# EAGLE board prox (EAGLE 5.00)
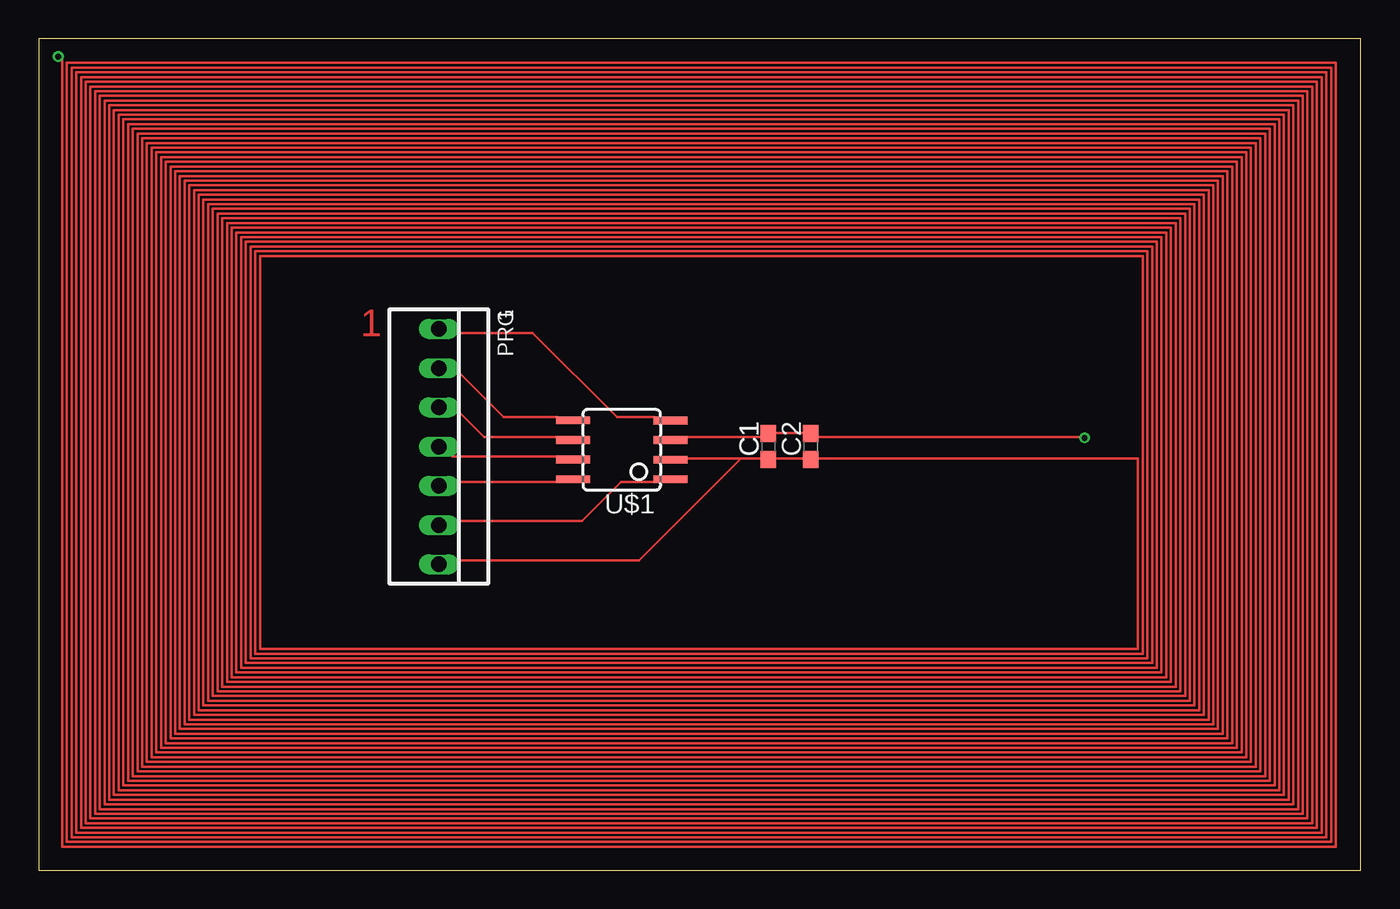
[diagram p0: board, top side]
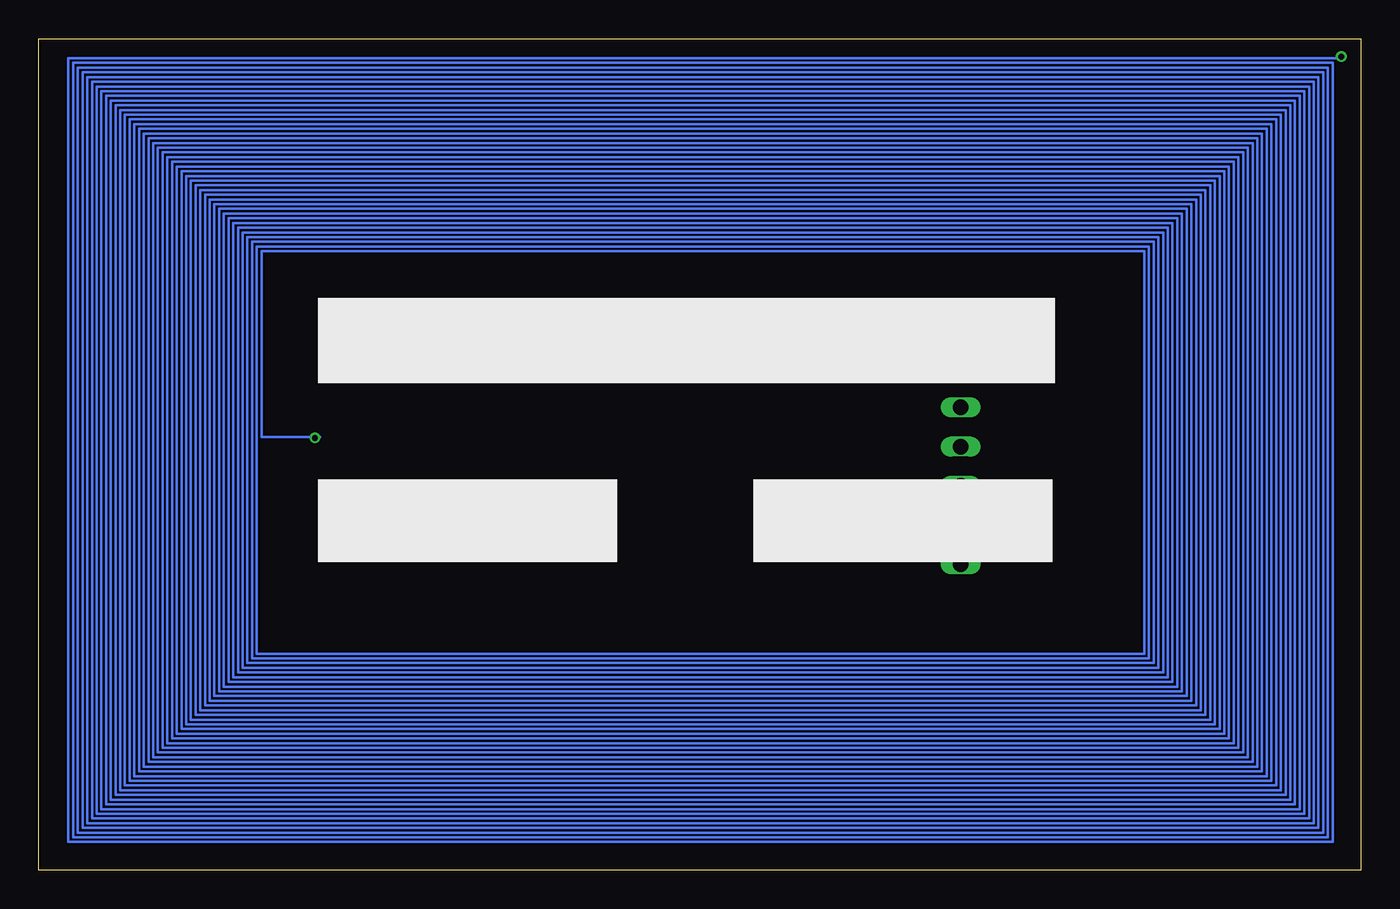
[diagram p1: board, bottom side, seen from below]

Size 85.6 x 53.85 mm. Coordinates in mm from the lower left corner, seen from the top.
Outline: 0,0 85.6,0 85.6,53.85 0,53.85 0,0
Copper layers (1*16): Top 0.035mm / dielectric 1.5mm / Bottom 0.035mm
Design rules "default *": minimum track width 6mil, minimum drill 15mil, track to track 6mil, track to pad 6mil, pad to pad 6mil, via to via 6mil, smd to smd 6mil, copper to edge 40mil, drill to drill 15mil, minimum pad ring 6mil, minimum via ring 6mil, stop-mask expansion 4mil, vias tented up to drill 0mil, thermal gap 10mil

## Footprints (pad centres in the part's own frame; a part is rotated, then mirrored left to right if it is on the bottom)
C0603 = smd 1.1 x 1: 1 -0.85,0; 2 0.85,0
22-23-2071 = drill 1 long: 1 -7.62,0; 2 -5.08,0; 3 -2.54,0; 4 0,0; 5 2.54,0; 6 5.08,0; 7 7.62,0
SOIC8 = smd 0.5 x 2.2: 1 -1.905,-3.154; 2 -0.645,-3.154; 3 0.625,-3.154; 4 1.895,-3.154; 5 1.905,3.154; 6 0.635,3.154; 7 -0.635,3.154; 8 -1.905,3.154

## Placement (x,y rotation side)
C1  [C0603]  47.24,27.43 90 top
C2  [C0603]  49.99,27.43 90 top
PRG  [22-23-2071]  25.91,27.43 270 top
U$1  TINY25/45/85-20SU  [SOIC8]  37.74,27.23 90 top

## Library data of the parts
C1 C2 = rcl
PRG = con-molex
U$1 = avr-7

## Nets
N$1: PRG.1 U$1.4
N$2: PRG.2 U$1.5
N$3: PRG.3 U$1.6
N$4: PRG.4 U$1.7
N$5: PRG.5 U$1.8
N$6: PRG.6 U$1.1
N$7: C1.1 C2.1 PRG.7 U$1.2
N$8: C1.2 C2.2 U$1.3

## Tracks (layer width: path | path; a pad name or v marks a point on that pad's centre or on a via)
N$1
  Top 0.152: U$1.4 39.88,29.34 37.44,29.34 31.98,34.8 27.18,34.8 PRG.1
N$2
  Top 0.152: U$1.5 33.53,29.34 30.1,29.34 27.18,32.26 PRG.2
N$3
  Top 0.152: U$1.6 33.53,28.07 28.83,28.07 27.18,29.72 PRG.3
N$4
  Top 0.152: U$1.7 33.53,26.8 26.8,26.8 PRG.4
N$5
  Top 0.152: U$1.8 33.53,25.15 27.18,25.15 PRG.5
N$6
  Top 0.152: U$1.1 39.88,25.15 37.72,25.15 35.18,22.61 27.18,22.61 PRG.6
N$7
  Top 0.152: C2.1 49.53,26.67 47.62,26.67 C1.1 46.86,26.67 45.47,26.67 | 45.47,26.67 41.91,26.67 U$1.2 | 45.47,26.67 38.86,20.07 27.18,20.07 PRG.7
N$8
  Top 0.152: C2.2 49.53,28.32 47.62,28.32 C1.2 46.86,28.07 41.91,28.07 U$1.3
N$9
  Top 0.152: 50.14,26.67 71.17,26.67 71.17,14.33 14.33,14.33 14.33,39.78 71.48,39.78 71.48,14.02 14.02,14.02 14.02,40.08 71.78,40.08 71.78,13.72 13.72,13.72 13.72,40.39 72.08,40.39 72.08,13.41 13.41,13.41 13.41,40.69 72.39,40.69 72.39,13.11 13.11,13.11 13.11,41 72.69,41 72.69,12.8 12.8,12.8 12.8,41.3 73,41.3 73,12.5 12.5,12.5 12.5,41.6 73.3,41.6 73.3,12.19 12.19,12.19 12.19,41.91 73.61,41.91 73.61,11.89 11.89,11.89 11.89,42.22 73.91,42.22 73.91,11.58 11.58,11.58 11.58,42.52 74.22,42.52 74.22,11.28 11.28,11.28 11.28,42.82 74.52,42.82 74.52,10.97 10.97,10.97 10.97,43.13 74.83,43.13 74.83,10.67 10.67,10.67 10.67,43.43 75.13,43.43 75.13,10.36 10.36,10.36 10.36,43.74 75.44,43.74 75.44,10.06 10.06,10.06 10.06,44.04 75.74,44.04 75.74,9.75 9.75,9.75 9.75,44.35 76.05,44.35 76.05,9.45 9.45,9.45 9.45,44.65 76.35,44.65 76.35,9.14 9.14,9.14 9.14,44.96 76.66,44.96 76.66,8.84 8.84,8.84 8.84,45.26 76.96,45.26 76.96,8.53 8.53,8.53 8.53,45.57 77.27,45.57 77.27,8.23 8.23,8.23 8.23,45.87 77.57,45.87 77.57,7.92 7.92,7.92 7.92,46.18 77.88,46.18 77.88,7.62 7.62,7.62 7.62,46.48 78.18,46.48 78.18,7.32 7.32,7.32 7.32,46.79 78.49,46.79 78.49,7.01 7.01,7.01 7.01,47.09 78.79,47.09 78.79,6.71 6.71,6.71 6.71,47.4 79.1,47.4 79.1,6.4 6.4,6.4 6.4,47.7 79.4,47.7 79.4,6.1 6.1,6.1 6.1,48.01 79.7,48.01 79.7,5.79 5.79,5.79 5.79,48.31 80.01,48.31 80.01,5.49 5.49,5.49 5.49,48.62 80.31,48.62 80.31,5.18 5.18,5.18 5.18,48.92 80.62,48.92 80.62,4.88 4.88,4.88 4.88,49.23 80.92,49.23 80.92,4.57 4.57,4.57 4.57,49.53 81.23,49.53 81.23,4.27 4.27,4.27 4.27,49.84 81.53,49.84 81.53,3.96 3.96,3.96 3.96,50.14 81.84,50.14 81.84,3.66 3.66,3.66 3.66,50.44 82.14,50.44 82.14,3.35 3.35,3.35 3.35,50.75 82.45,50.75 82.45,3.05 3.05,3.05 3.05,51.05 82.75,51.05 82.75,2.74 2.74,2.74 2.74,51.36 83.06,51.36 83.06,2.44 2.44,2.44 2.44,51.66 83.36,51.66 83.36,2.13 2.13,2.13 2.13,51.97 83.67,51.97 83.67,1.83 1.83,1.83 1.83,52.27 83.97,52.27
N$10
  Top 0.152: 83.97,52.27 83.97,1.52 1.52,1.52 1.52,52.73
N$11
  Bottom 0.152: 67.36,28.04 71.17,28.04 71.17,40.08 14.02,40.08 14.02,14.02 71.48,14.02 71.48,40.39 13.72,40.39 13.72,13.72 71.78,13.72 71.78,40.69 13.41,40.69 13.41,13.41 72.08,13.41 72.08,41 13.11,41 13.11,13.11 72.39,13.11 72.39,41.3 12.8,41.3 12.8,12.8 72.69,12.8 72.69,41.6 12.5,41.6 12.5,12.5 73,12.5 73,41.91 12.19,41.91 12.19,12.19 73.3,12.19 73.3,42.22 11.89,42.22 11.89,11.89 73.61,11.89 73.61,42.52 11.58,42.52 11.58,11.58 73.91,11.58 73.91,42.82 11.28,42.82 11.28,11.28 74.22,11.28 74.22,43.13 10.97,43.13 10.97,10.97 74.52,10.97 74.52,43.43 10.67,43.43 10.67,10.67 74.83,10.67 74.83,43.74 10.36,43.74 10.36,10.36 75.13,10.36 75.13,44.04 10.06,44.04 10.06,10.06 75.44,10.06 75.44,44.35 9.75,44.35 9.75,9.75 75.74,9.75 75.74,44.65 9.45,44.65 9.45,9.45 76.05,9.45 76.05,44.96 9.14,44.96 9.14,9.14 76.35,9.14 76.35,45.26 8.84,45.26 8.84,8.84 76.66,8.84 76.66,45.57 8.53,45.57 8.53,8.53 76.96,8.53 76.96,45.87 8.23,45.87 8.23,8.23 77.27,8.23 77.27,46.18 7.92,46.18 7.92,7.92 77.57,7.92 77.57,46.48 7.62,46.48 7.62,7.62 77.88,7.62 77.88,46.79 7.32,46.79 7.32,7.32 78.18,7.32 78.18,47.09 7.01,47.09 7.01,7.01 78.49,7.01 78.49,47.4 6.71,47.4 6.71,6.71 78.79,6.71 78.79,47.7 6.4,47.7 6.4,6.4 79.1,6.4 79.1,48.01 6.1,48.01 6.1,6.1 79.4,6.1 79.4,48.31 5.79,48.31 5.79,5.79 79.7,5.79 79.7,48.62 5.49,48.62 5.49,5.49 80.01,5.49 80.01,48.92 5.18,48.92 5.18,5.18 80.31,5.18 80.31,49.23 4.88,49.23 4.88,4.88 80.62,4.88 80.62,49.53 4.57,49.53 4.57,4.57 80.92,4.57 80.92,49.84 4.27,49.84 4.27,4.27 81.23,4.27 81.23,50.14 3.96,50.14 3.96,3.96 81.53,3.96 81.53,50.44 3.66,50.44 3.66,3.66 81.84,3.66 81.84,50.75 3.35,50.75 3.35,3.35 82.14,3.35 82.14,51.05 3.05,51.05 3.05,3.05 82.45,3.05 82.45,51.36 2.74,51.36 2.74,2.74 82.75,2.74 82.75,51.66 2.44,51.66 2.44,2.44 83.06,2.44 83.06,51.97 2.13,51.97 2.13,2.13 83.36,2.13 83.36,52.27 1.83,52.27 1.83,1.83 83.67,1.83 83.67,52.58
N$12  (via drill 0.38)
  other vias: 1.27,52.68
N$13  (via drill 0.38)
  other vias: 67.72,27.99
N$14
  Top 0.152: 50.14,28.04 67.67,28.04
N$15
  Bottom 0.152: 1.22,52.58 83.67,52.58

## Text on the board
Top: 1
_tsilk: 1 | C1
